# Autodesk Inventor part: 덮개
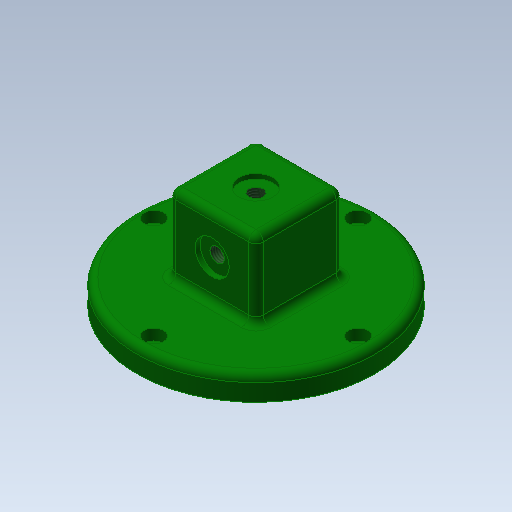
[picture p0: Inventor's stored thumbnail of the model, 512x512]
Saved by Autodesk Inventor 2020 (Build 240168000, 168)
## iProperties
Created: 2017-08
Part Number: 덮개
Material: 알루미늄 6061
Document SubType Name: Modeling
Designer: mduedu
Density: 1 g/cm^3
Appearance: 진녹색
Author: mduedu
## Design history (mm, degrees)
sketch "스케치1"
  geometry: C1 r 49 at (0, 0); 1 further point
  constraints: 1 centre point, 1 coincident
  dimensions: "d55" = 98 diameter of C1
extrude "돌출1" new body sketch "스케치1" distance "d5" = 10; taper "d6" = 0 deg
sketch "스케치2"
  geometry: L1 (-18, -18)-(18, -18); L2 (18, -18)-(18, 18); L3 (18, 18)-(-18, 18); L4 (-18, 18)-(-18, -18); L5 (-18, -18)-(18, 18); L6 (18, -18)-(-18, 18); 1 further point
  constraints: 12 end point, 2 midpoint, 2 parallel, 2 perpendicular, 1 horizontal
  dimensions: "d7" = 36 distance of L2.end L3.end
extrude "돌출2" join sketch "스케치2" distance "d9" = 32; taper "d10" = 0 deg
sketch "스케치3"
  geometry: C1 r 37 at (0, 0); 1 further point
  constraints: 1 centre point, 1 coincident
  dimensions: "d56" = 74 diameter of C1
extrude "돌출3" join sketch "스케치3" distance "d12" = 7; taper "d13" = 0 deg
sketch "스케치4"
  geometry: C1 r 33 at (0, 0); 1 further point
  constraints: 1 centre point, 1 coincident
  dimensions: "d57" = 66 diameter of C1
extrude "돌출4" cut sketch "스케치4" distance "d16" = 6; taper "d17" = 0 deg
sketch "스케치5"
  geometry: C1 r 9 at (0, 0); 1 further point
  constraints: 1 centre point, 1 coincident
  dimensions: "d18" = 18 diameter of C1
extrude "돌출5" cut sketch "스케치5" distance "d19" = 34; taper "d20" = 0 deg
sketch "스케치6"
  geometry: 2 further points
  constraints: 1 coincident
hole "구멍1" sketch "스케치6" at (0, 0) diameter "d21" = 5.917; stored, may be unused: countersink angle "d25" = 90 deg, drill point angle "d27" = 118 deg; dims "d22" = 6, "d23" = 14, "d24" = 2, "d26" = 8
sketch "스케치7"
  geometry: L1 (-31, -10)-(67, -10) reference; 3 further points
  constraints: 1 midpoint, 1 vertical alignment
  dimensions: "d58" = 26 distance from line of point (18, 16) L1
hole "구멍2" sketch "스케치7" at (18, 16) diameter "d29" = 5.917; stored, may be unused: countersink angle "d33" = 90 deg, drill point angle "d35" = 118 deg; dims "d30" = 6, "d31" = 14, "d32" = 2, "d34" = 8
fillet "모깎기2" dims "d37" = 3
fillet "모깎기3" dims "d38" = 3
fillet "모깎기4" dims "d39" = 3
fillet "모깎기5" dims "d40" = 3
chamfer "모따기1" distance "d41" = 1; stored, may be unused: second distance "d42" = 2, angle "d43" = 45 deg
fillet "모깎기7" dims "d45" = 3
fillet "모깎기8" dims "d46" = 3
sketch "스케치10" dims "d59" = 84
  geometry: 3 further points
  constraints: 2 vertical alignment, 1 coincident, 2 other
hole "구멍4" sketch "스케치10" at (0, 42) diameter "d60" = 4.5; stored, may be unused: countersink angle "d64" = 90 deg, drill point angle "d66" = 118 deg; dims "d61" = 6, "d62" = 8, "d63" = 4.6, "d65" = 8
node "솔리드1"
pattern_circular "원형 패턴1" dims angle "d68" = 360 deg
